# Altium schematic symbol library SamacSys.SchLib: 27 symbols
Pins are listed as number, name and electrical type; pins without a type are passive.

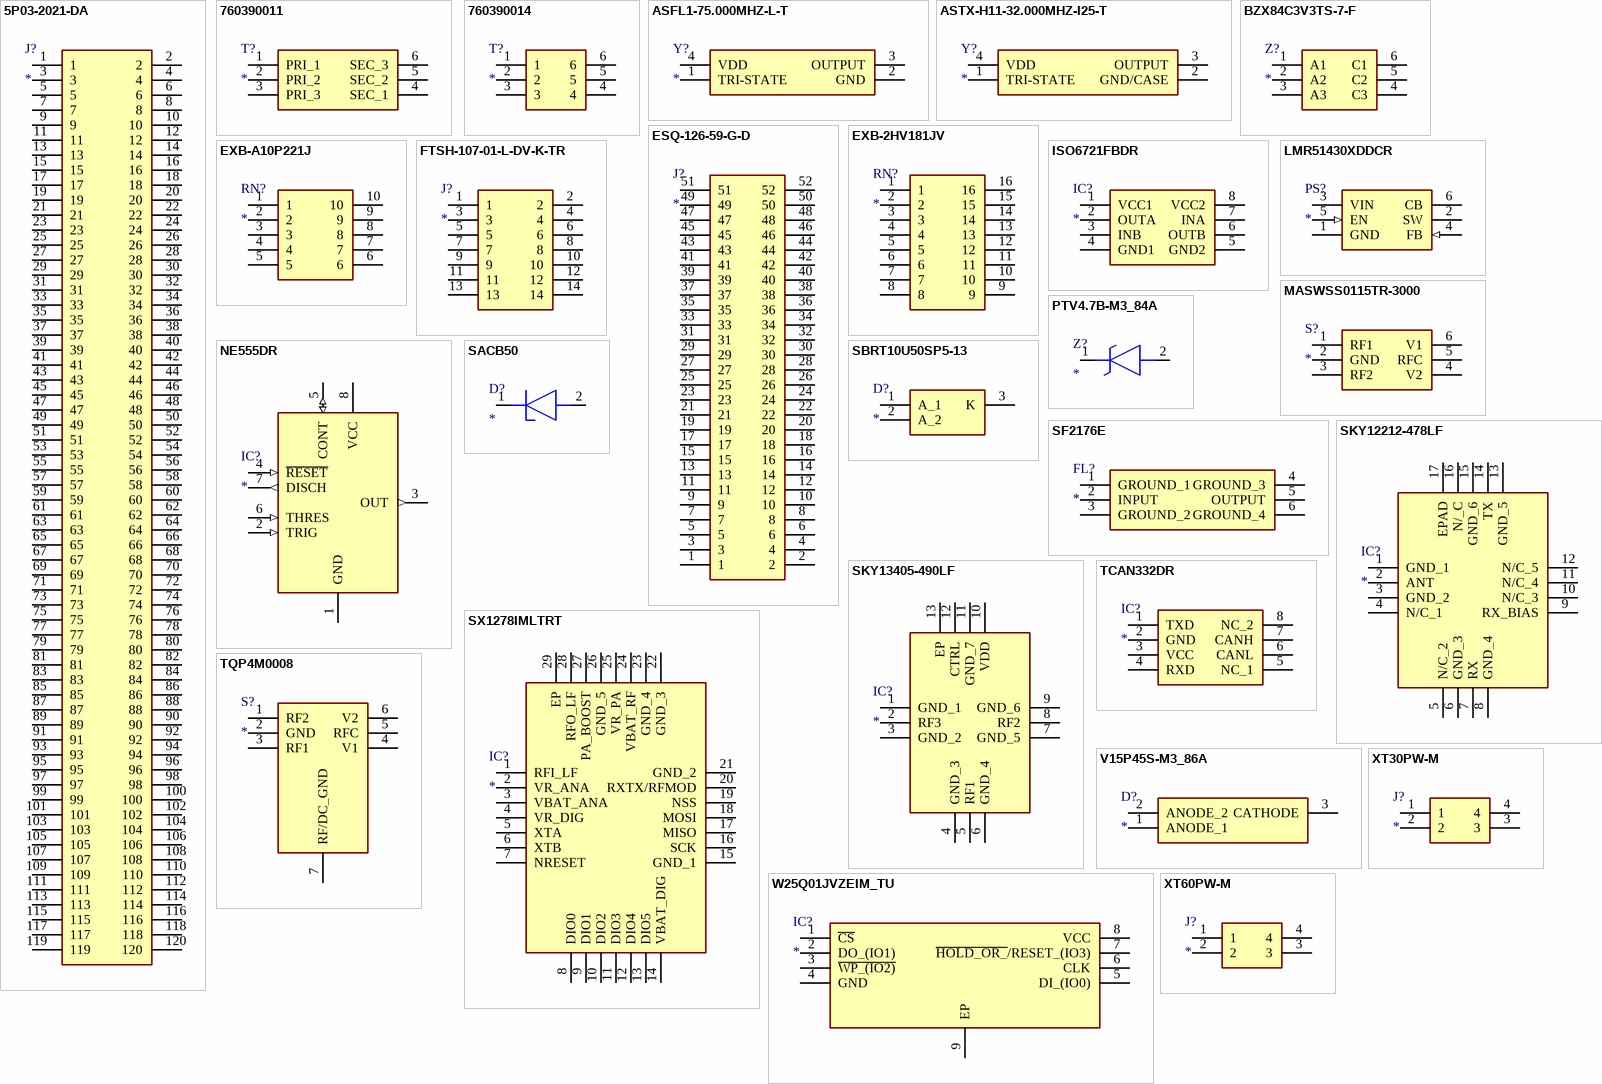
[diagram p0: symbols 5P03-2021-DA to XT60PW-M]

## 5P03-2021-DA
designator J?
Connector; Manufacturer_Name: 3M; Manufacturer_Part_Number: 5P03-2021-DA; Description: Conn PC/104 Plus Connector 120 POS 2mm Press Fit ST Thru-Hole Box
footprint RHDR120W70P200_4X30_6040X800X955P
pins: 1, 2, 3, 4, 5, 6, 7, 8, 9, 10, 11, 12, 13, 14, 15, 16, 17, 18, 19, 20, 21, 22, 23, 24, 25, 26, 27, 28, 29, 30, 31, 32, 33, 34, 35, 36, 37, 38, 39, 40, 41, 42, 43, 44, 45, 46, 47, 48, 49, 50, 51, 52, 53, 54, 55, 56, 57, 58, 59, 60, 61, 62, 63, 64, 65, 66, 67, 68, 69, 70, 71, 72, 73, 74, 75, 76, 77, 78, 79, 80, 81, 82, 83, 84, 85, 86, 87, 88, 89, 90, 91, 92, 93, 94, 95, 96, 97, 98, 99, 100, 101, 102, 103, 104, 105, 106, 107, 108, 109, 110, 111, 112, 113, 114, 115, 116, 117, 118, 119, 120

## 760390011
designator T?
Transformer; Manufacturer_Name: Wurth Elektronik; Manufacturer_Part_Number: 760390011
footprint 760390011
pins: 1 PRI_1, 2 PRI_2, 3 PRI_3, 4 SEC_1, 5 SEC_2, 6 SEC_3

## 760390014
designator T?
Transformer; Manufacturer_Name: Wurth Elektronik; Manufacturer_Part_Number: 760390014
footprint 760390015
pins: 1, 2, 3, 4, 5, 6

## ASFL1-75.000MHZ-L-T
designator Y?
Crystal or Oscillator; Manufacturer_Name: ABRACON; Manufacturer_Part_Number: ASFL1-75.000MHZ-L-T
footprint ASFL1
pins: 1 TRI-STATE, 2 GND, 3 OUTPUT, 4 VDD

## ASTX-H11-32.000MHZ-I25-T
designator Y?
Crystal or Oscillator; Manufacturer_Name: ABRACON; Manufacturer_Part_Number: ASTX-H11-32.000MHZ-I25-T
footprint ASTXH1124576MHZT
pins: 1 TRI-STATE, 2 GND/CASE, 3 OUTPUT, 4 VDD

## BZX84C3V3TS-7-F
designator Z?
Zener Diode; Manufacturer_Name: Diodes Incorporated; Manufacturer_Part_Number: BZX84C3V3TS-7-F
footprint SOT65P210X110-6N
pins: 1 A1, 2 A2, 3 A3, 4 C3, 5 C2, 6 C1

## ESQ-126-59-G-D
designator J?
Connector; Manufacturer_Name: SAMTEC; Manufacturer_Part_Number: ESQ-126-59-G-D
footprint ESQ-126-Y-X-D
pins: 1, 2, 3, 4, 5, 6, 7, 8, 9, 10, 11, 12, 13, 14, 15, 16, 17, 18, 19, 20, 21, 22, 23, 24, 25, 26, 27, 28, 29, 30, 31, 32, 33, 34, 35, 36, 37, 38, 39, 40, 41, 42, 43, 44, 45, 46, 47, 48, 49, 50, 51, 52

## EXB-2HV181JV
designator RN?
Resistor Network; Manufacturer_Name: Panasonic; Manufacturer_Part_Number: EXB-2HV181JV
footprint EXB2HV_1
pins: 1, 2, 3, 4, 5, 6, 7, 8, 9, 10, 11, 12, 13, 14, 15, 16

## EXB-A10P221J
designator RN?
Resistor Network; Manufacturer_Name: Panasonic; Manufacturer_Part_Number: EXB-A10P221J
footprint EXBA10P221J
pins: 1, 2, 3, 4, 5, 6, 7, 8, 9, 10

## FTSH-107-01-L-DV-K-TR
designator J?
Connector; Manufacturer_Name: SAMTEC; Manufacturer_Part_Number: FTSH-107-01-L-DV-K-TR
footprint FTSH10701LDVKTR
pins: 1, 2, 3, 4, 5, 6, 7, 8, 9, 10, 11, 12, 13, 14

## ISO6721FBDR
designator IC?
Integrated Circuit; Manufacturer_Name: Texas Instruments; Manufacturer_Part_Number: ISO6721FBDR
footprint SOIC127P600X175-8N
pins: 1 VCC1, 2 OUTA, 3 INB, 4 GND1, 5 GND2, 6 OUTB, 7 INA, 8 VCC2

## LMR51430XDDCR
designator PS?
Power Supply; Manufacturer_Name: Texas Instruments; Manufacturer_Part_Number: LMR51430XDDCR
footprint SOT95P280X110-6N
pins: 1 GND (power), 2 SW (power), 3 VIN (power), 4 FB (in), 5 EN (in), 6 CB (power)

## MASWSS0115TR-3000
designator S?
Switch; Manufacturer_Name: MACOM; Manufacturer_Part_Number: MASWSS0115TR-3000
footprint SOT65P210X110-6N
pins: 1 RF1, 2 GND (power), 3 RF2, 4 V2, 5 RFC, 6 V1

## NE555DR
designator IC?
Integrated Circuit; Manufacturer_Name: Texas Instruments; Manufacturer_Part_Number: NE555DR
footprint SOIC127P600X175-8N
pins: 1 GND (power), 2 TRIG (in), 3 OUT (out), 4 ~{RESET} (in), 5 CONT (io), 6 THRES (in), 7 DISCH (out), 8 VCC (power)

## PTV4.7B-M3_84A
designator Z?
Zener Diode; Manufacturer_Name: Vishay; Manufacturer_Part_Number: PTV4.7B-M3/84A
footprint PTV47BM384A
pins: 1 K, 2 A

## SACB50
designator D?
Diode ESD (Uni-directional); Manufacturer_Name: LITTELFUSE; Manufacturer_Part_Number: SACB50
footprint DIOM5436X244N
pins: 1 K, 2 A

## SBRT10U50SP5-13
designator D?
Diode; Manufacturer_Name: Diodes Incorporated; Manufacturer_Part_Number: SBRT10U50SP5-13
footprint SBRT10U50SP513
pins: 1 A_1, 2 A_2, 3 K

## SF2176E
designator FL?
Filter; Manufacturer_Name: RFMi; Manufacturer_Part_Number: SF2176E
footprint SF2176E
pins: 1 GROUND_1, 2 INPUT, 3 GROUND_2, 4 GROUND_3, 5 OUTPUT, 6 GROUND_4

## SKY12212-478LF
designator IC?
Integrated Circuit; Manufacturer_Name: Skyworks; Manufacturer_Part_Number: SKY12212-478LF
footprint QFN65P400X400X160-17N-D
pins: 1 GND_1, 2 ANT, 3 GND_2, 4 N/C_1, 5 N/C_2, 6 GND_3, 7 RX, 8 GND_4, 9 RX_BIAS, 10 N/C_3, 11 N/C_4, 12 N/C_5, 13 GND_5, 14 TX, 15 GND_6, 16 N/_C, 17 EPAD

## SKY13405-490LF
designator IC?
Integrated Circuit; Manufacturer_Name: Skyworks; Manufacturer_Part_Number: SKY13405-490LF
footprint SKY13405490LF
pins: 1 GND_1, 2 RF3, 3 GND_2, 4 GND_3, 5 RF1, 6 GND_4, 7 GND_5, 8 RF2, 9 GND_6, 10 VDD, 11 GND_7, 12 CTRL, 13 EP

## SX1278IMLTRT
designator IC?
Integrated Circuit; Manufacturer_Name: SEMTECH; Manufacturer_Part_Number: SX1278IMLTRT
footprint QFN65P600X600X100-29N-D
pins: 1 RFI_LF, 2 VR_ANA, 3 VBAT_ANA, 4 VR_DIG, 5 XTA, 6 XTB, 7 NRESET, 8 DIO0, 9 DIO1, 10 DIO2, 11 DIO3, 12 DIO4, 13 DIO5, 14 VBAT_DIG, 15 GND_1, 16 SCK, 17 MISO, 18 MOSI, 19 NSS, 20 RXTX/RFMOD, 21 GND_2, 22 GND_3, 23 GND_4, 24 VBAT_RF, 25 VR_PA, 26 GND_5, 27 PA_BOOST, 28 RFO_LF, 29 EP

## TCAN332DR
designator IC?
Integrated Circuit; Manufacturer_Name: Texas Instruments; Manufacturer_Part_Number: TCAN332DR
footprint SOIC127P600X175-8N
pins: 1 TXD, 2 GND, 3 VCC, 4 RXD, 5 NC_1, 6 CANL, 7 CANH, 8 NC_2

## TQP4M0008
designator S?
Switch; Manufacturer_Name: Qorvo; Manufacturer_Part_Number: TQP4M0008
footprint SON50P200X200X90-7N-D
pins: 1 RF2, 2 GND, 3 RF1, 4 V1, 5 RFC, 6 V2, 7 RF/DC_GND

## V15P45S-M3_86A
designator D?
Schottky Diode; Manufacturer_Name: Vishay; Manufacturer_Part_Number: V15P45S-M3/86A
footprint V15P45SM386A
pins: 1 ANODE_1, 2 ANODE_2, 3 CATHODE

## W25Q01JVZEIM_TU
designator IC?
Integrated Circuit; Manufacturer_Name: Winbond; Manufacturer_Part_Number: W25Q01JVZEIM TU
footprint SON127P800X600X80-9N-D
pins: 1 ~{CS}, 2 DO_(IO1), 3 ~{WP_(IO2)}, 4 GND, 5 DI_(IO0), 6 CLK, 7 ~{HOLD_OR_}/RESET_(IO3), 8 VCC, 9 EP

## XT30PW-M
designator J?
Connector; Manufacturer_Name: Amass; Manufacturer_Part_Number: XT30PW-M
footprint XT30PWM
pins: 1, 2, 3, 4

## XT60PW-M
designator J?
Connector; Manufacturer_Name: Changzou Amass Elec; Manufacturer_Part_Number: XT60PW-M
footprint XT60PWM
pins: 1, 2, 3, 4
